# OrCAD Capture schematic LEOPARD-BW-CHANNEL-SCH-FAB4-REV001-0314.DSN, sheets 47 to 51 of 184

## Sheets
47 180_CPU - XDP: size A3; title: CPU - XDP
48 179_PCH - NOA: size A3; title: PCH - NOA
49 178_PCH - XDP: size A3; title: PCH - XDP
50 139_CPLD OTHERS: size Custom; title: CPLD OTHERS
51 138_CPLD FOR BOOT UP: size A3; title: CPLD FOR BOOT UP

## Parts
sheet 138_CPLD FOR BOOT UP
C464  SCD1U16V2KX-3GP  [C402H22]
C465  SC1KP50V2KX-1GP  [C402H22]
C466  SC1KP50V2KX-1GP  [C402H22]
C467  SC10U6D3V5KX-4GP  [C805H58]
C468  SCD1U16V2KX-3GP  [C402H22]
C469  SCD1U16V2KX-3GP  [C402H22]
C470  SCD1U16V2KX-3GP  [C402H22]
C471  SCD1U16V2KX-3GP  [C402H22]
C472  SCD1U16V2KX-3GP  [C402H22]
C473  SCD1U16V2KX-3GP  [C402H22]
C474  SCD1U16V2KX-3GP  [C402H22]
C475  SCD1U16V2KX-3GP  [C402H22]
C476  SCD01U25V2KX-3GP  [C402H22]
C477  SCD01U25V2KX-3GP  [C402H22]
CPLD1  LCMXO256C-3MN100C-GP  [BGA100G80H54]
R175  200R2J-L1-GP  [R402H16]
R176  200R2J-L1-GP  [R402H16]
R489  0R2J-2-GP  [R402H16]
R491  0R2J-2-GP  [R402H16]
R540  0R2J-2-GP  [R402H16]
R552  4K7R2J-2-GP  [R402H16]
R553  10KR2F-2-GP  [R402H16]
R554  4K75R2F-1-GP  [R402H16]
R555  10KR2F-2-GP  [R402H16]
R556  10KR2F-2-GP  [R402H16]
R557  10KR2F-2-GP  [R402H16]
R558  10KR2F-2-GP  [R402H16]
R559  1KR2F-3-GP  [R402H16]
R560  1KR2F-3-GP  [R402H16]
R561  1KR2F-3-GP  [R402H16]
R562  10KR2F-2-GP  [R402H16]
R563  0R2J-2-GP  [R402H16]
R564  0R2J-2-GP  [R402H16]
R565  0R2J-2-GP  [R402H16]
R566  0R2J-2-GP  [R402H16]
R614  10KR2F-2-GP  [R402H16]
R854  10KR2F-2-GP  [R402H16]
R858  10KR2F-2-GP  [R402H16]
R860  1KR2F-3-GP  [R402H16]
R870  10KR2F-2-GP  [R402H16]
R883  0R2J-2-GP  [R402H16]
R884  0R2J-2-GP  [R402H16]
R887  10KR2F-2-GP  [R402H16]
R1089  2KR2F-3-GP  [R402H16]
R1090  1KR2F-3-GP  [R402H16]
R1091  2KR2F-3-GP  [R402H16]
R1092  1KR2F-3-GP  [R402H16]
TP342  TPAD24  [TPAD24]
TP344  TPAD24  [TPAD24]
TP345  TPAD24  [TPAD24]
sheet 139_CPLD OTHERS
C293  SCD1U16V2KX-3GP  [C402H22]
C432  SC1U10V2KX-4-GP  [C402H22]
C481  SCD1U16V2KX-3GP  [C402H22]
C482  SCD01U25V2KX-3GP  [C402H22]
C514  SCD1U16V2KX-3GP  [C402H22]
CN51  JWT-CONN12D-SFP9-GP  [A2541WV0-2CX6PA-6T-N1]
LED46  LED-G-62-GP-U  [LED1608AKH36]
LED47  LED-G-62-GP-U  [LED1608AKH36]
LED48  LED-G-62-GP-U  [LED1608AKH36]
LED49  LED-G-62-GP-U  [LED1608AKH36]
LED50  LED-G-62-GP-U  [LED1608AKH36]
Q13  LMBT3904LT1G-GP  [SOT23CBE2D4H44]
Q14  LMBT3904LT1G-GP  [SOT23CBE2D4H44]
Q15  LMBT3904LT1G-GP  [SOT23CBE2D4H44]
Q16  LMBT3904LT1G-GP  [SOT23CBE2D4H44]
Q17  LMBT3904LT1G-GP  [SOT23CBE2D4H44]
R2  0R2J-2-GP  [R402H16]
R12  0R2J-2-GP  [R402H16]
R235  0R2J-2-GP  [R402H16]
R281  0R2J-2-GP  [R402H16]
R327  0R2J-2-GP  [R402H16]
R334  0R2J-2-GP  [R402H16]
R351  0R2J-2-GP  [R402H16]
R630  1KR2F-3-GP  [R402H16]
R631  1KR2F-3-GP  [R402H16]
R684  220R2F-GP  [R402H16]
R863  10KR2F-2-GP  [R402H16]
R864  10KR2F-2-GP  [R402H16]
R991  22R2F-1-GP  [R402H16]
R994  0R2J-2-GP  [R402H16]
R1040  10KR2F-2-GP  [R402H16]
R1093  0R2J-2-GP  [R402H16]
R1110  0R2J-2-GP  [R402H16]
R1111  0R2J-2-GP  [R402H16]
R1112  0R2J-2-GP  [R402H16]
R1119  1KR2F-3-GP  [R402H16]
R1142  2K43R2F-GP  [R402H16]
R1143  330R2J-3-GP  [R402H16]
R1144  330R2J-3-GP  [R402H16]
R1145  2K43R2F-GP  [R402H16]
R1146  2K43R2F-GP  [R402H16]
R1147  330R2J-3-GP  [R402H16]
R1148  2K43R2F-GP  [R402H16]
R1149  330R2J-3-GP  [R402H16]
R1150  2K43R2F-GP  [R402H16]
R1151  330R2J-3-GP  [R402H16]
R1152  0R2J-2-GP  [R402H16]
R1153  22R2F-1-GP  [R402H16]
R1154  10KR2F-2-GP  [R402H16]
R1256  0R2J-2-GP  [R402H16]
TP46  TPAD24  [TPAD24]
TP188  TPAD24  [TPAD24]
TP222  TPAD24  [TPAD24]
TP223  TPAD24  [TPAD24]
TP224  TPAD24  [TPAD24]
TP225  TPAD24  [TPAD24]
U81  PI3B3257QE-GP  [QSOIC16H69]
sheet 178_PCH - XDP
R1898  160R2F-GP  [R402H16]
R1899  160R2F-GP  [R402H16]
R1900  160R2F-GP  [R402H16]
R1901  51R2F-2-GP  [R402H16]
R1902  75R2F-2-GP  [R402H16]
R1903  75R2F-2-GP  [R402H16]
R1904  75R2F-2-GP  [R402H16]
R1905  4K7R2J-2-GP  [R402H16]
sheet 179_PCH - NOA
R195  10KR2F-2-GP  [R402H16]
R954  0R2J-2-GP  [R402H16]
R955  0R2J-2-GP  [R402H16]
R956  0R2J-2-GP  [R402H16]
R957  0R2J-2-GP  [R402H16]
R958  0R2J-2-GP  [R402H16]
R962  0R2J-2-GP  [R402H16]
R966  0R2J-2-GP  [R402H16]
R968  0R2J-2-GP  [R402H16]
R970  0R2J-2-GP  [R402H16]
R971  0R2J-2-GP  [R402H16]
R975  0R2J-2-GP  [R402H16]
sheet 180_CPU - XDP
C708  SC1U10V2KX-4-GP  [C402H22]
C709  SC1U10V2KX-4-GP  [C402H22]
C710  SCD1U16V2KX-3GP  [C402H22]
C711  SCD1U16V2KX-3GP  [C402H22]
C712  SCD1U16V2KX-3GP  [C402H22]
C713  SCD1U16V2KX-3GP  [C402H22]
R988  1KR2F-3-GP  [R402H16]
R989  1KR2F-3-GP  [R402H16]
R990  0R2J-2-GP  [R402H16]
R992  1KR2F-3-GP  [R402H16]
R993  475R2F-L1-GP  [R402H16]
R995  100R2F-L1-GP-U  [R402H14]
R996  100R2F-L1-GP-U  [R402H14]
R997  1KR2F-3-GP  [R402H16]
R998  150R2F-1-GP  [R402H16]
R999  1KR2F-3-GP  [R402H16]
TP301  TPAD24  [TPAD24]
TP302  TPAD24  [TPAD24]
TP303  TPAD24  [TPAD24]
TP304  TPAD24  [TPAD24]
TP305  TPAD24  [TPAD24]
TP306  TPAD24  [TPAD24]
TP307  TPAD24  [TPAD24]
TP308  TPAD24  [TPAD24]
TP309  TPAD24  [TPAD24]
TP310  TPAD24  [TPAD24]
TP311  TPAD24  [TPAD24]
TP312  TPAD24  [TPAD24]
TP442  TPAD24  [TPAD24]
XDPCN1  SMC-CONN60A-GP  [BSH-03001-FDA]

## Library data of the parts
C464 C514 = SCD1U16V2KX-3GP: CHIP CAP C 0.1U 16V K0402 X7R; CATEGORIES: CAP_1.xV; GREENDFACTOR: R2_SA;HF_SA;G_SA;; MAIN_SOURCE: M; Part Number: 78.10421.2FL; Part Type: SMD-BCG; SPEC: http://wpqssvr.wistron.com.tw:7001/wpqs/servlet/COM.qpart.Attachment?PartNumber=78.10421.2FL
C465 C466 = SC1KP50V2KX-1GP: CHIP CAP 1000P50V K0402 X7R(RO; Category: Powervill; GREENDFACTOR: R2_SA;HF_SA;G_SA;; Package Type: SMD-BCG; Part Number: 78.10224.2FL; Quotation: 9_7; Type: SMD
C467 = SC10U6D3V5KX-4GP: CHIP CAP C 10U 6.3V K0805 X7R; Category: CLK GEN; GREENDFACTOR: R_SA;HF_SA;G_SA;; Part Number: 78.10620.21L; Quotation: 13_8; Type: SMD
C293 C468-C475 C481 C710-C713 = SCD1U16V2KX-3GP: CHIP CAP C 0.1U 16V K0402 X7R; Category: CLK GEN; GREENDFACTOR: R_SA;HF_SA;G_SA;; Part Number: 78.10421.2FL; Quotation: 13_8; Type: SMD
C476 C477 C482 = SCD01U25V2KX-3GP: CHIP 0.01U 25V K0402 X7R(ROHS); Category: CLK GEN; GREENDFACTOR: R2_SA;HF_SA;G_SA;; Package Type: SMD-BCG; Part Number: 78.10322.2FL; Quotation: 13_8; Type: SMD
CPLD1 = LCMXO256C-3MN100C-GP: IC CPLD LCMXO256C-3MN100C CSBGA 100P; POP?: 073.00256.0I0U; Part Number: 73.00256.0VU; Part Type: ASIC-G3
R175 R176 = 200R2J-L1-GP: CHIP RES 200 J 1/16W 0402; Category: CPU SIDE BAND; Part Number: 63.20134.1DL; Part Type: SMD-RG
R489 R491 R540 = 0R2J-2-GP: CHIP RES 0 J 1/16W 0402; Category: PCH; DESCRIPTIO: CHIP RES 0 J 1/16W 0402; GREENDFACTOR: R2_SA;HF_SA;G_SA;; Package Type: SMD-RG; Part Number: 63.R0034.1DL; Part Type: SMD-RG; SPEC: http://wpqssvr.wistron.com.tw:7001/wpqs/servlet/COM.qpart.Attachment?PartNumber=63.R0034.1DL; VENDORPARTNUMBER: RM04JTN0/RTT02000JTH/RR0510X-000-XN/RC0402JR-070RL/WR04X000 PTL
R552 = 4K7R2J-2-GP: CHIP RES 4.7K J 1/16W 0402; Category: SMBUS; GREENDFACTOR: R_SA;HF_SA;G_SA;; Part Number: 63.47234.1DL; Quotation: 8_1; Type: SMD
R553 R556-R558 R562 R614 R858 R863 R864 R870 R887 R1040 = 10KR2F-2-GP: CHIP RES 10K F 1/16W 0402; Category: MSIC; DESCRIPTIO: CHIP RES 10K F 1/16W 0402; GREENDFACTOR: R2_SA;HF_SA;G_SA;; Package Type: SMD-RG; Part Number: 64.10025.6DL; Part Type: SMD-RG; SPEC: http://wpqssvr.wistron.com.tw:7001/wpqs/servlet/COM.qpart.Attachment?PartNumber=64.10025.6DL; VENDORPARTNUMBER: RM04FTN1002 / RTT021002FTH / RR0510S-103-FN / RC0402FR-0710KL/WR04X1002FTL
R554 = 4K75R2F-1-GP: CHIP RES 4.75K F 1/16W 0402; Category: VR_DDR; GREENDFACTOR: R2_SA;HF_SA;G_SA;; Package Type: RCL_GP; Part Number: 64.47515.6DL; Part Type: RCL_GP; SPEC: http://wpqssvr.wistron.com.tw:7001/wpqs/servlet/COM.qpart.Attachment?PartNumber=64.47515.6DL; VENDORPARTNUMBER: RM04FTN4751/RTT024751FTH/RR0510S-4751-FN/RC0402FR-074K75L
R555 R854 R1154 = 10KR2F-2-GP: CHIP RES 10K F 1/16W 0402; Category: MSIC; DESCRIPTIO: CHIP RES 10K F 1/16W 0402; GREENDFACTOR: R2_SA;HF_SA;G_SA;; POP?: NOPOP; Package Type: SMD-RG; Part Number: 64.10025.6DL; Part Type: SMD-RG; SPEC: http://wpqssvr.wistron.com.tw:7001/wpqs/servlet/COM.qpart.Attachment?PartNumber=64.10025.6DL; VENDORPARTNUMBER: RM04FTN1002 / RTT021002FTH / RR0510S-103-FN / RC0402FR-0710KL/WR04X1002FTL
R559 R631 R988 R989 R992 R997 R999 = 1KR2F-3-GP: CHIP RES 1K F 1/16W 0402; Category: internal conn; GREENDFACTOR: R2_SA;HF_SA;G_SA;; Package Type: SMD-RG; Part Number: 64.10015.6DL; Part Type: SMD-RG; SPEC: http://wpqssvr.wistron.com.tw:7001/wpqs/servlet/COM.qpart.Attachment?PartNumber=64.10015.6DL; VENDORPARTNUMBER: RM04FTN1001 / RTT021001FTH / RR0510S-1001-FN / RC0402FR-071KL/WR04X1001FTL
R560 R561 R630 R860 R1119 = 1KR2F-3-GP: CHIP RES 1K F 1/16W 0402; Category: internal conn; GREENDFACTOR: R2_SA;HF_SA;G_SA;; POP?: NOPOP; Package Type: SMD-RG; Part Number: 64.10015.6DL; Part Type: SMD-RG; SPEC: http://wpqssvr.wistron.com.tw:7001/wpqs/servlet/COM.qpart.Attachment?PartNumber=64.10015.6DL; VENDORPARTNUMBER: RM04FTN1001 / RTT021001FTH / RR0510S-1001-FN / RC0402FR-071KL/WR04X1001FTL
R563-R566 R954-R956 R958 R966 R968 R970 R971 R975 R990 = 0R2J-2-GP: CHIP RES 0 J 1/16W 0402; Category: BMC; DESCRIPTIO: CHIP RES 0 J 1/16W 0402; GREENDFACTOR: R2_SA;HF_SA;G_SA;; Package Type: SMD-RG; Part Number: 63.R0034.1DL; Part Type: SMD-RG; SPEC: http://wpqssvr.wistron.com.tw:7001/wpqs/servlet/COM.qpart.Attachment?PartNumber=63.R0034.1DL; VENDORPARTNUMBER: RM04JTN0/RTT02000JTH/RR0510X-000-XN/RC0402JR-070RL/WR04X000 PTL
R883 R884 R957 R962 = 0R2J-2-GP: CHIP RES 0 J 1/16W 0402; Category: BMC; DESCRIPTIO: CHIP RES 0 J 1/16W 0402; GREENDFACTOR: R2_SA;HF_SA;G_SA;; POP?: NOPOP; Package Type: SMD-RG; Part Number: 63.R0034.1DL; Part Type: SMD-RG; SPEC: http://wpqssvr.wistron.com.tw:7001/wpqs/servlet/COM.qpart.Attachment?PartNumber=63.R0034.1DL; VENDORPARTNUMBER: RM04JTN0/RTT02000JTH/RR0510X-000-XN/RC0402JR-070RL/WR04X000 PTL
R1089 R1091 = 2KR2F-3-GP: CHIP RES 2K F 1/16W 0402; Category: internal conn; DESCRIPTIO: CHIP RES 2K F 1/16W 0402; GREENDFACTOR: R2_SA;HF_SA;G_SA;; Package Type: SMD-RG; Part Number: 64.20015.6DL; Part Type: SMD-RG; SPEC: http://wpqssvr.wistron.com.tw:7001/wpqs/servlet/COM.qpart.Attachment?PartNumber=64.20015.6DL; VENDORPARTNUMBER: RM04FTN2001 / RTT022001FTH / RR0510S-202-FN / RC0402FR-072KL/WR04X2001FTL
R1090 R1092 = 1KR2F-3-GP: CHIP RES 1K F 1/16W 0402; GREENDFACTOR: R2_SA;HF_SA;G_SA;; Part Number: 64.10015.6DL; Part Type: SMD-RG; SPEC: http://wpqssvr.wistron.com.tw:7001/wpqs/servlet/COM.qpart.Attachment?PartNumber=64.10015.6DL
TP46 TP188 TP222-TP225 TP301-TP312 TP342 TP344 TP345 TP442 = TPAD24: 24 MILS TEST PAD; Part Number: ZZ.PAD24.001; Part Type: DISCRET2
C432 = SC1U10V2KX-4-GP: CHIP CAP C 1U 10V K 0402 X6S; GREENDFACTOR: R2_SA;HF_SA;; POP?: NOPOP; Part Number: 78.10523.8FL; Part Type: SMD-BCG6; SPEC: http://wpqssvr.wistron.com.tw:7001/wpqs/servlet/COM.qpart.Attachment?PartNumber=78.10523.8FL
CN51 = JWT-CONN12D-SFP9-GP: HEAD ML 2R12P(-1#11) A2541WV0-2CX6PA-6T; GREENDFACTOR: R2_SA;; Part Number: 21.62906.206; Part Type: CONN-G3; SPEC: http://wpqssvr.wistron.com.tw:7001/wpqs/servlet/COM.qpart.Attachment?PartNumber=21.62906.206
LED46-LED50 = LED-G-62-GP-U: LED GREEN LTST-C190GKT SMD; GREENDFACTOR: R2_SA;; Package Type: DISCRET-G9; Part Number: 83.00190.Q70; SPEC: http://wpqssvr.wistron.com.tw:7001/wpqs/servlet/COM.qpart.Attachment?PartNumber=83.00190.Q70
Q13-Q17 = LMBT3904LT1G-GP: XTOR LMBT3904LT1G NPN SOT-23; GREENDFACTOR: R2_SA;HF_SA;G_SA;; Part Number: 84.T3904.H11; Part Type: DISCRET-G6; SPEC: http://wpqssvr.wistron.com.tw:7001/wpqs/servlet/COM.qpart.Attachment?PartNumber=84.T3904.H11
R2 R12 R235 R281 R327 R334 R351 R1152 R1256 = 0R2J-2-GP: CHIP RES 0 J 1/16W 0402; Category: LOM - i350; DESCRIPTIO: CHIP RES 0 J 1/16W 0402; GREENDFACTOR: R2_SA;HF_SA;G_SA;; POP?: NOPOP; Package Type: SMD-RG; Part Number: 63.R0034.1DL; Part Type: SMD-RG; SPEC: http://wpqssvr.wistron.com.tw:7001/wpqs/servlet/COM.qpart.Attachment?PartNumber=63.R0034.1DL; VENDORPARTNUMBER: RM04JTN0/RTT02000JTH/RR0510X-000-XN/RC0402JR-070RL/WR04X000 PTL
R684 = 220R2F-GP: CHIP RES 220 F 1/16W 0402; Category: CPU0; GREENDFACTOR: R2_SA;HF_SA;G_SA;; Package Type: RCL_GP; Part Number: 64.22005.6DL; SPEC: http://wpqssvr.wistron.com.tw:7001/wpqs/servlet/COM.qpart.Attachment?PartNumber=64.22005.6DL
R991 R1153 = 22D1R2F-GP: CHIP RES 22 F 1/16W 0402(ROHS); Category: Logic; DESCRIPTIO: CHIP RES 22.1 F 1/16W 0402; GREENDFACTOR: R2_SA;HF_SA;G_SA;; Package Type: SMD-RG; Part Number: 64.22R05.6DL; Part Type: SMD-RG; SPEC: http://wpqssvr.wistron.com.tw:7001/wpqs/servlet/COM.qpart.Attachment?PartNumber=64.22R05.6DL; VENDORPARTNUMBER: RM04FTN22R0/RTT0222R0FTH/RR0510S-220-FN/RC0402FR-0722RL
R994 R1093 R1110-R1112 = 0R2J-2-GP: CHIP RES 0 J 1/16W 0402; Category: LOM - i350; DESCRIPTIO: CHIP RES 0 J 1/16W 0402; GREENDFACTOR: R2_SA;HF_SA;G_SA;; Package Type: SMD-RG; Part Number: 63.R0034.1DL; Part Type: SMD-RG; SPEC: http://wpqssvr.wistron.com.tw:7001/wpqs/servlet/COM.qpart.Attachment?PartNumber=63.R0034.1DL; VENDORPARTNUMBER: RM04JTN0/RTT02000JTH/RR0510X-000-XN/RC0402JR-070RL/WR04X000 PTL
R1142 R1145 R1146 R1148 R1150 = 2K43R2F-GP: CHIP RES 2.43K F 1/16W 0402; GREENDFACTOR: R2_SA;HF_SA;G_SA;; Package Type: RCL_GP; Part Number: 64.24315.6DL; SPEC: http://wpqssvr.wistron.com.tw:7001/wpqs/servlet/COM.qpart.Attachment?PartNumber=64.24315.6DL
R1143 R1144 R1147 R1149 R1151 = 330R2J-3-GP: CHIP RES 330 J 1/16W 0402; Category: HW monitor; DESCRIPTIO: CHIP RES 330 J 1/16W 0402; GREENDFACTOR: R2_SA;HF_SA;G_SA;; Package Type: SMD-RG; Part Number: 63.33134.1DL; Part Type: SMD-RG; SPEC: http://wpqssvr.wistron.com.tw:7001/wpqs/servlet/COM.qpart.Attachment?PartNumber=63.33134.1DL; VENDORPARTNUMBER: RM04JTN331 / RTT02331JTH / RR0510S-331-JN / RC0402JR-07330RL/WR04X331JTL
U81 = PI3B3257QE-GP: IC BUS SW PI3B3257QE QSOP 16P; GREENDFACTOR: R2_SA;; Package Type: DISCRET-G2; Part Number: 73.33257.A0C; SPEC: http://wpqssvr.wistron.com.tw:7001/wpqs/servlet/COM.qpart.Attachment?PartNumber=73.33257.A0C
R1898-R1900 = 160R2F-GP: CHIP RES 160 F 1/16W 0402; GREENDFACTOR: R2_SA;HF_SA;G_SA;; Package Type: SMD-RG1; Part Number: 64.16005.6DL; SPEC: http://wpqssvr.wistron.com.tw:7001/wpqs/servlet/COM.qpart.Attachment?PartNumber=64.16005.6DL
R1901 = 51D1R2F-GP: CHIP RES 51 F 1/16W 0402; Category: XDP; DESCRIPTIO: CHIP RES 51.1 F 1/16W 0402; GREENDFACTOR: R2_SA;HF_SA;G_SA;; Package Type: SMD-RG; Part Number: 64.51R05.6DL; Part Type: SMD-RG; SPEC: http://wpqssvr.wistron.com.tw:7001/wpqs/servlet/COM.qpart.Attachment?PartNumber=64.51R05.6DL; VENDORPARTNUMBER: RM04FTN51R0/RTT0251R0FTH/RR0510S-510-FN/RC0402FR-0751RL/WR04X51R0FTL
R1902-R1904 = 75R2F-2-GP: CHIP RES 75 F 1/16W 0402; Category: XDP; DESCRIPTIO: CHIP RES 75 F 1/16W 0402; GREENDFACTOR: R2_SA;HF_SA;G_SA;; Package Type: SMD-RG; Part Number: 64.75R05.6DL; Part Type: SMD-RG; SPEC: http://wpqssvr.wistron.com.tw:7001/wpqs/servlet/COM.qpart.Attachment?PartNumber=64.75R05.6DL; VENDORPARTNUMBER: RM04FTN75R0 / RTT0275R0FTH / RR0510S-750-FN / RC0402FR-0775RL/WR04X75R0FTL
R1905 = 4K7R2J-2-GP: CHIP RES 4.7K J 1/16W 0402; Category: PCH; GREENDFACTOR: R_SA;HF_SA;G_SA;; Part Number: 63.47234.1DL; Quotation: 8_1; Type: SMD
R195 = 10KR2F-2-GP: CHIP RES 10K F 1/16W 0402; Category: PCH; DESCRIPTIO: CHIP RES 10K F 1/16W 0402; GREENDFACTOR: R2_SA;HF_SA;G_SA;; Package Type: SMD-RG; Part Number: 64.10025.6DL; Part Type: SMD-RG; SPEC: http://wpqssvr.wistron.com.tw:7001/wpqs/servlet/COM.qpart.Attachment?PartNumber=64.10025.6DL; VENDORPARTNUMBER: RM04FTN1002 / RTT021002FTH / RR0510S-103-FN / RC0402FR-0710KL/WR04X1002FTL
C708 C709 = SC1U10V2KX-4-GP: CHIP CAP C 1U 10V K 0402 X6S; GREENDFACTOR: R2_SA;HF_SA;; Part Number: 78.10523.8FL; Part Type: SMD-BCG6; SPEC: http://wpqssvr.wistron.com.tw:7001/wpqs/servlet/COM.qpart.Attachment?PartNumber=78.10523.8FL
R993 = 475R2F-L1-GP: CHIP RES 475 F 1/16W 0402; Category: Clock; DESCRIPTIO: CHIP RES 475 F 1/16W 0402; GREENDFACTOR: R2_SA;HF_SA;G_SA;; Package Type: SMD-RG; Part Number: 64.47505.6DL; Part Type: SMD-RG; SPEC: http://wpqssvr.wistron.com.tw:7001/wpqs/servlet/COM.qpart.Attachment?PartNumber=64.47505.6DL; VENDORPARTNUMBER: RM04FTN4750 / RTT024750FTH / RR0510S-4750-FN / RC0402FR-07475RL/WR04X4750FTL
R995 R996 = 100R2F-L1-GP-U: CHIP RES 100 F 1/16W 0402; Category: CPU SIDE BAND; Part Number: 64.10005.6DL; Part Type: SMD-RG
R998 = 150R2F-1-GP: CHIP RES 150 F 1/16W 0402; Category: VR_DDR; DESCRIPTIO: CHIP RES 150 F 1/16W 0402; GREENDFACTOR: R2_SA;HF_SA;G_SA;; Package Type: SMD-RG; Part Number: 64.15005.6DL; Part Type: SMD-RG; SPEC: http://wpqssvr.wistron.com.tw:7001/wpqs/servlet/COM.qpart.Attachment?PartNumber=64.15005.6DL; VENDORPARTNUMBER: RM04FTN1500 / RTT021500FTH / RR0510S-1500-FN / RC0402FR-07150RL/WR04X1500FTL
XDPCN1 = SMC-CONN60A-GP: CONN SMD 60P BSH-030-01-L-D-A-; Category: XDP; DESCRIPTIO: CONN SMD 60P BSH-030-01-L-D-A-; GREENDFACTOR: R2_SA;HF_SA;; Note: The same as CRB; Package Type: CONN-G6; Part Number: 20.F0441.060; Part Type: CONN-G6; SPEC: http://wpqssvr.wistron.com.tw:7001/wpqs/servlet/COM.qpart.Attachment?PartNumber=20.F0441.060; VENDORPARTNUMBER: BSH-030-01-L-D-A-TR

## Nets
GND: C293.2 C432.2 C464.2 C465.2 C466.2 C467.2 C468.2 C469.2 C470.2 C471.2 C472.2 C473.2 C474.2 C475.2 C476.2 C477.2 C481.2 C482.2 C514.2 C708.2 C709.2 C710.2 C711.2 C712.2 C713.2 CN51.1 CN51.12 CPLD1.A4(GNDIO0) CPLD1.B9(GND) CPLD1.B13(GNDIO0) CPLD1.C13(PR3B) CPLD1.G14(GNDIO0) CPLD1.H1(GNDIO1) CPLD1.N2(GNDIO1) CPLD1.N3(PB2B) CPLD1.N9(GND) CPLD1.N10(GNDIO1) Q13.E Q14.E Q15.E Q16.E Q17.E R554.2 R558.2 R559.2 R560.2 R561.2 R562.2 R630.2 R631.2 R684.2 R860.2 R870.2 R1040.1 R1089.2 R1090.2 R1091.2 R1092.1 R1256.1 R1901.2 R1902.2 R1903.2 R1904.2 TP225.1 U81.8(GND) XDPCN1.1 XDPCN1.2 XDPCN1.7 XDPCN1.8 XDPCN1.13 XDPCN1.14 XDPCN1.19 XDPCN1.20 XDPCN1.25 XDPCN1.26 XDPCN1.31 XDPCN1.32 XDPCN1.37 XDPCN1.38 XDPCN1.49 XDPCN1.50 XDPCN1.59 ; also on sheet 1 2 3 4 5 6 7 8 9 10 11 12 13 14 15 16 17 18 19 20 21 22 23 24 25 26 27 28 29 30 31 32 33 34 35 36 37 38 39 44 46 52 53 54 55 56 57 58 59 60 61 62 63 64 65 66 69 70 71 73 74 75 76 78 79 80 81 82 83 84 86 87 88 89 90 91 92 93 94 95 96 97 98 99 100 101 102 103 104 105 106 107 108 109 110 111 112 113 114 115 116 117 118 119 128 129 138 139 159 160 161 166 168 169 170 171 172 173 174 175 176 177 180 181 182 183 184
P3V3: R195.1 R1905.1 ; also on sheet 1 3 8 45 46 52 54 58 65 74 76 78 83 84 87 90 91 94 95 96 100 101 102 161 166 168 173 174 177 180 181 182 183
P3V3_STBY: C293.1 C432.1 C467.1 C468.1 C469.1 C470.1 C471.1 C472.1 C473.1 C474.1 C475.1 C476.1 C477.1 C481.1 C482.1 C514.1 CN51.2 CPLD1.A14(VCCIO0) CPLD1.B5(VCCIO0) CPLD1.B6(VCC) CPLD1.B7(VCCAUX) CPLD1.G1(VCCIO1) CPLD1.H14(VCCIO0) CPLD1.P1(VCCIO1) CPLD1.P7(VCC) CPLD1.P10(VCCIO1) R175.1 R176.1 R552.1 R553.1 R555.1 R556.1 R557.1 R614.1 R854.1 R858.1 R863.1 R864.1 R887.2 R992.2 R997.2 R999.2 R1119.1 R1143.1 R1144.2 R1147.2 R1149.2 R1151.2 R1154.1 R1898.1 R1899.1 R1900.1 U81.16(VCC) ; also on sheet 2 3 5 6 8 9 10 11 12 15 16 17 20 21 22 25 26 27 30 31 33 34 35 37 38 39 45 52 54 55 59 60 61 62 63 64 65 66 69 70 71 72 73 74 76 79 83 84 87 88 89 90 91 92 93 94 95 96 97 98 99 159 161 166 168 173 174 176 177 179 180 182 183 184
PVCCIN_CPU0_EN: CPLD1.D2(PL3A) R1089.1 ; also on sheet 39
PVCCIN_CPU1_EN: CPLD1.K2(PL7A) R1091.1 ; also on sheet 35
PVCCIO: C708.1 C709.1 R993.2 R995.2 R996.2 R998.2 XDPCN1.43 XDPCN1.44 ; also on sheet 11 16 26 35 39 46 68 87 97 100 101 102 103 120 129 130 139 160 173 177 179 182
ARM_TCK: R2.1 R12.1 R1110.1 ; also on sheet 177
ARM_TDI: R334.1 R1112.1 ; also on sheet 177
ARM_TDO: R351.1 R1111.1 ; also on sheet 177
ARM_TMS: R235.1 R281.1 R1093.1 ; also on sheet 177
BMC_JTAG_SELECT: R1040.2 R1119.2 U81.1(S) ; also on sheet 74
BMC_READY_R: CPLD1.J13(PR6B) R884.1
BMC_RESET_N: R883.2 ; also on sheet 74 177
BMC_RESET_R_N: CPLD1.L14(PR8A) R883.1
BMC_TCK: R1110.2 U81.12(4A)
BMC_TDI: R1112.2 U81.7(2A)
BMC_TDO: R1111.2 U81.4(1A)
BMC_TMS: R1093.2 U81.9(3A)
BOARD_ID0_PCH: R966.2 ; also on sheet 71
BOARD_ID2_PCH: R968.2 ; also on sheet 71
CLK_32K_SUSCLK_NGFF: R1152.2 ; also on sheet 83
CLK_32K_SUSCLK_PLD: R991.1 ; also on sheet 55
CLK_32K_SUSCLK_PLD_R: R991.2 R1152.1
CLK_33K_SUSCLK_PLD: R1153.1 ; also on sheet 90 174
CLK_33K_SUSCLK_PLD_R: R994.1 R1153.2
CLK_33K_SUSCLK_PLD_R2: CPLD1.A7(PT3D) R994.2
CLK_100M_XDP_DN: XDPCN1.42 ; also on sheet 88
CLK_100M_XDP_DP: XDPCN1.40 ; also on sheet 88
CPLD1_OK_HB: CPLD1.A6(PT3C) ; also on sheet 177
CPU_CACHE_FLUSH_TRIGGER_N: R962.1 ; also on sheet 92
FM_ADR_COMPLETE: R540.2 ; also on sheet 166 177
FM_ADR_COMPLETE_CPLD_SAVE: CPLD1.B11(PT5B) ; also on sheet 52
FM_BMC_READY_N: R884.2 ; also on sheet 52 74 166
FM_CPLD_ADR_COMPLETE: CPLD1.N14(PR9B) R540.1
FM_CPU0_BDX_PRSNT_LVT3_N: CPLD1.L1(PL7B) ; also on sheet 11 139 179
FM_CPU0_SKTOCC_LVT3_N: CPLD1.M3(PL9A) ; also on sheet 46 139 179
FM_CPU1_BDX_PRSNT_LVT3_N: CPLD1.D1(PL3B) ; also on sheet 129 179
FM_CPU1_SKTOCC_LVT3_N: CPLD1.J2(PL6A) ; also on sheet 46 129 179
FM_CPU_ERR1_CO_N: CPLD1.L2(PL7C) R552.2 ; also on sheet 102 177
FM_CPU_PROCHOT_N: R195.2 R971.2 ; also on sheet 98
FM_ERR1_DLY_N: CPLD1.B10(PT4D) ; also on sheet 166
FM_LVC3_THERMTRIP_DLY: CPLD1.P14(PB5C) ; also on sheet 182
FM_P3V3_CPLD_EN: CPLD1.G2(PL5B) ; also on sheet 3
FM_PCH_PRSNT_CO_N: CPLD1.B8(PT4A) ; also on sheet 89
FM_PERST_SRC_LVT3: CPLD1.P11(PB4A) R631.1 R1154.2
FM_PLD_CLK_EN: CPLD1.B3(PT2E) ; also on sheet 58
FM_PLD_DEBUG1: CPLD1.L13(PR8B) R863.2 R1142.1 R1256.2 TP46.1
FM_PLD_DEBUG1_R: Q13.B R1142.2
FM_PLD_DEBUG2: CPLD1.A9(PT4C) R1145.1 TP188.1
FM_PLD_DEBUG2_R: Q14.B R1145.2
FM_PLD_DEBUG3: CPLD1.A5(PT3B) R1146.1 TP222.1
FM_PLD_DEBUG3_R: Q15.B R1146.2
FM_PLD_DEBUG4: CPLD1.G13(PR5D) R1148.1 TP223.1
FM_PLD_DEBUG4_R: Q16.B R1148.2
FM_PLD_DEBUG5: CPLD1.A3(PT2F) R1150.1 TP224.1
FM_PLD_DEBUG5_R: Q17.B R1150.2
FM_PLD_DEBUG_MODE_N: CPLD1.M2(PL8A) R630.1 R864.2
FM_PLD_RESET_N: CPLD1.J1(PL5D) R556.2 R560.1
FM_PLD_TSALL: CPLD1.K1(PL6B) R555.2 R559.1
FM_PS_EN: CPLD1.A2(PT2D) ; also on sheet 59 93
FM_SLPS3_N: CPLD1.B4(PT3A) ; also on sheet 52 59 74 90
FM_SLPS4_N: CPLD1.A1(PT2B) ; also on sheet 74 90
FM_THERMTRIP_CO_N: CPLD1.M1(PL7D) R553.2 ; also on sheet 98
FM_VCC_MAIN_EN: CPLD1.A8(PT4B) ; also on sheet 10 11
FM_VPP_MEM_ABCD_EN: CPLD1.N11(PB4B) R1092.2 ; also on sheet 22 27
FM_VPP_MEM_EFGH_EN: CPLD1.J14(PR7A) R1090.1 ; also on sheet 12 17
FM_XDP_HOOK1_SEL: CPLD1.P8(PB3B) R858.2 R860.1
FP_PWR_BTN_N: CPLD1.N7(PB3A) ; also on sheet 168
IRQ_SML1_PMBUS_ALERT_BUF_N: CPLD1.E13(PR4B) ; also on sheet 52 183
JTAG_PLD1_TCK: CN51.7 R12.2 U81.13(4B2) ; also on sheet 52
JTAG_PLD1_TDI: CN51.3 R327.2 U81.6(2B2) ; also on sheet 52
JTAG_PLD1_TDO: CN51.9 R351.2 U81.3(1B2) ; also on sheet 52
JTAG_PLD1_TMS: CN51.5 R281.2 U81.10(3B2) ; also on sheet 52
JTAG_PLD_TCK: CN51.6 CPLD1.N4(TCK) R2.2 R554.1 U81.14(4B1)
JTAG_PLD_TDI: CN51.10 CPLD1.P6(TDI) R334.2 U81.5(2B1)
JTAG_PLD_TDO: CN51.4 CPLD1.P5(TDO) R327.1 U81.2(1B1) ; also on sheet 84
JTAG_PLD_TMS: CN51.8 CPLD1.P2(TMS) R235.2 U81.11(3B1)
LED_DEBUG1: LED46.A R1143.2
LED_DEBUG1_R: LED46.K Q13.C
LED_DEBUG2: LED47.A R1144.1
LED_DEBUG2_R: LED47.K Q14.C
LED_DEBUG3: LED48.A R1147.1
LED_DEBUG3_R: LED48.K Q15.C
LED_DEBUG4: LED49.A R1149.1
LED_DEBUG4_R: LED49.K Q16.C
LED_DEBUG5: LED50.A R1151.1
LED_DEBUG5_R: LED50.K Q17.C
NOA_0_FM_USB_OC_0_N: R954.1 ; also on sheet 92
NOA_1_FM_USB_OC_1_N: R956.1 ; also on sheet 92
NOA_2_FM_USB_OC_2_N: R957.1 ; also on sheet 92
NOA_3_FM_USB_OC_3_N: R958.1 ; also on sheet 92
NOA_5_FM_USB_OC_5_N: R966.1 ; also on sheet 92
NOA_6_FM_USB_OC_6_N: R968.1 ; also on sheet 92
NOA_7_FM_USB_OC_7_N: R970.1 ; also on sheet 92
NOA_9_RST_PCIE_PCH_N: R955.1 R1905.2 ; also on sheet 91
NOA_13_FM_CPU_PROCHOT_N: R971.1 ; also on sheet 91
NOA_14_GP18_TP: R975.1 ; also on sheet 90
NVDIMM_PRSNT_R: CPLD1.B14(PR3A) ; also on sheet 177
PCH_GP56_PLD_TCK: R854.2 ; also on sheet 166
POWER_FAIL_1_R: R957.2 ; also on sheet 54
POWER_FAIL_N: R962.2 ; also on sheet 52 54 61 93 177
PU_PLD_SLEEP_N: CPLD1.M12(SLEEP#) R557.2 R561.1
PWRGD_CPU0_G: R988.1 ; also on sheet 97 139
PWRGD_CPU0_LVC3: R563.2 ; also on sheet 97
PWRGD_CPU0_LVC3_R: CPLD1.C3(PT2C) R563.1
PWRGD_CPU1_LVC3: R564.1 ; also on sheet 97
PWRGD_CPU1_LVC3_R: CPLD1.E2(PL4A) R564.2
PWRGD_CPUPWRGD: CPLD1.B1(PL2A) ; also on sheet 182
PWRGD_LOM_AUX_VRS: CPLD1.C12(PR2B) R887.1
PWRGD_P1V05_PCH: CPLD1.C2(PL3C) ; also on sheet 10
PWRGD_P1V5_PCH: CPLD1.N1(PL8B) ; also on sheet 8 11
PWRGD_P1V05_PCH_STBY_DLY: CPLD1.P3(PL9B) ; also on sheet 90 174
PWRGD_P1V05_STBY_PCH_P1V0_STBY: CPLD1.P4(PB2A) ; also on sheet 9
PWRGD_P3V3: CPLD1.B12(PT4F) ; also on sheet 3 8
PWRGD_P5V: CPLD1.P9(PB3D) ; also on sheet 59
PWRGD_PCH_PWROK: CPLD1.C1(PL2B) ; also on sheet 52 90 174
PWRGD_PS_PWROK: C464.1 CPLD1.F1(PL4B) ; also on sheet 59 65
PWRGD_PVCCIN_CPU0: C465.1 CPLD1.A13(PR2A) ; also on sheet 39 58
PWRGD_PVCCIN_CPU1: C466.1 CPLD1.A10(PT4E) ; also on sheet 35
PWRGD_PVPP_PVDDQ_AB: CPLD1.P12(PB4C) ; also on sheet 31
PWRGD_PVPP_PVDDQ_CD: CPLD1.N12(PB4D) ; also on sheet 26
PWRGD_PVPP_PVDDQ_EF: CPLD1.E14(PR5A) ; also on sheet 21
PWRGD_PVPP_PVDDQ_GH: CPLD1.H13(PR6A) ; also on sheet 16
PWRGD_SYS_PWROK: CPLD1.H2(PL5C) ; also on sheet 52 90 174
REVISION_ID3_PCH: R970.2 ; also on sheet 71
ROMA0: R958.2 ; also on sheet 72 180
RST_CPU0_G_N: R989.2 ; also on sheet 97 139
RST_CPU0_LVC3_N: R565.1 ; also on sheet 97 99
RST_CPU0_LVC3_R_N: CPLD1.F2(PL5A) R565.2
RST_CPU1_LVC3_N: R566.1 ; also on sheet 97 99
RST_CPU1_LVC3_R_N: CPLD1.E1(PL3D) R566.2
RST_DLY_CPURST_LVC3: CPLD1.C14(PR3C) ; also on sheet 181
RST_PCIE_CPU_N: CPLD1.M14(PR9A) R614.2 ; also on sheet 90
RST_PCIE_PCH_DEV_N: CPLD1.M13(PR7D) R870.1 ; also on sheet 64 74 83
RST_PCIE_PCH_N: CPLD1.K13(PR7B) R955.2 ; also on sheet 174
RST_PERST0_N: CPLD1.K14(PR7C) R562.1 ; also on sheet 93 94 95 168
RST_PERST1_N: R491.2 R558.1 TP345.1
RST_PERST1_R_N: CPLD1.F14(PR5C) R491.1
RST_PLTRST_BUF_N: R489.2 ; also on sheet 52 78 177
RST_PLTRST_BUF_N_R: CPLD1.F13(PR5B) R489.1
RST_PLTRST_DLY: CPLD1.A12(PT5C) ; also on sheet 183
RST_PLTRST_N: CPLD1.N8(PB3C) ; also on sheet 90 100 174 177
RST_RSMRST_N: CPLD1.P13(PB5A) ; also on sheet 52 177 182
SGPIO_BMC_CLK_BUF_LVC3: CPLD1.A11(PT5A) R176.2 TP342.1
SMB_HOST_STBY_LVC3_CLK: XDPCN1.53 ; also on sheet 55 74 77 90 161
SMB_HOST_STBY_LVC3_DATA: XDPCN1.51 ; also on sheet 55 74 77 90 161
SRP_CPU_PWR_DEBUG_N: C712.1 R998.1 XDPCN1.45 ; also on sheet 128 138
SSB_ROW_LATCH: R975.2 ; also on sheet 168
TP_SGPIO_BMC_LD_BUF_LVC3_N: CPLD1.D13(PR3D) R175.2 TP344.1
TP_XDP_CPU_OBSDATA_C_MBP2: TP303.1 XDPCN1.10
TP_XDP_CPU_OBSDATA_C_MBP3: TP304.1 XDPCN1.12
TP_XDP_CPU_OBSDATA_C_MBP4: TP305.1 XDPCN1.16
TP_XDP_CPU_OBSDATA_C_MBP5: TP306.1 XDPCN1.18
TP_XDP_CPU_OBSDATA_D_MBP2: TP309.1 XDPCN1.28
TP_XDP_CPU_OBSDATA_D_MBP3: TP310.1 XDPCN1.30
TP_XDP_CPU_OBSDATA_D_MBP4: TP311.1 XDPCN1.34
TP_XDP_CPU_OBSDATA_D_MBP5: TP312.1 XDPCN1.36
TP_XDP_CPU_OBSFN_C0: TP301.1 XDPCN1.4
TP_XDP_CPU_OBSFN_C1: TP302.1 XDPCN1.6
TP_XDP_CPU_OBSFN_D0: TP307.1 XDPCN1.22
TP_XDP_CPU_OBSFN_D1: TP308.1 XDPCN1.24
TP_XDP_CPU_TCK1: TP442.1 XDPCN1.55
U81_EN_N: R684.1 U81.15(OE#)
USB2_OC0_INT_N: R954.2 ; also on sheet 176
USB2_OC1_FP_N: R956.2 ; also on sheet 176
XDP_CPU0_OBSDATA_A_MBP2_G_N: XDPCN1.9 ; also on sheet 139
XDP_CPU0_OBSDATA_A_MBP3_G_N: XDPCN1.11 ; also on sheet 139
XDP_CPU0_OBSDATA_A_MBP4_G_N: XDPCN1.15 ; also on sheet 139
XDP_CPU0_OBSDATA_A_MBP5_G_N: XDPCN1.17 ; also on sheet 139
XDP_CPU0_PRDY_G_N: XDPCN1.5 ; also on sheet 46 139
XDP_CPU0_PREQ_G_N: XDPCN1.3 ; also on sheet 46 139
XDP_CPU1_OBSDATA_B_MBP2_G_N: XDPCN1.27 ; also on sheet 129
XDP_CPU1_OBSDATA_B_MBP3_G_N: XDPCN1.29 ; also on sheet 129
XDP_CPU1_OBSDATA_B_MBP4_G_N: XDPCN1.33 ; also on sheet 129
XDP_CPU1_OBSDATA_B_MBP5_G_N: XDPCN1.35 ; also on sheet 129
XDP_CPU_OBSFN_B_MBP6_G_N: R996.1 XDPCN1.21 ; also on sheet 129 139
XDP_CPU_OBSFN_B_MBP7_G_N: R995.1 XDPCN1.23 ; also on sheet 129 139
XDP_CPU_PWRGD: R988.2 XDPCN1.39
XDP_CPU_RST_N: R989.1 XDPCN1.46
XDP_CPU_SYSPWROK: C710.1 CPLD1.D14(PR4A) R992.1 XDPCN1.47
XDP_CPU_TCK_G: XDPCN1.57 ; also on sheet 46 129 139
XDP_CPU_TDI: XDPCN1.56 ; also on sheet 46
XDP_CPU_TDO: XDPCN1.52 ; also on sheet 46
XDP_CPU_TMS_G: XDPCN1.58 ; also on sheet 46 129 139
XDP_CPU_TRST_G_N: XDPCN1.54 ; also on sheet 46 129 139
XDP_PCH_TCK0: R1901.1 ; also on sheet 90
XDP_PCH_TDI: R1899.2 R1903.1 ; also on sheet 90
XDP_PCH_TDO: R1900.2 R1904.1 ; also on sheet 90
XDP_PCH_TMS: R1898.2 R1902.1 ; also on sheet 90
XDP_PRESENT_N: R990.2 R993.1 ; also on sheet 128 138
XDP_PRESENT_R_N: R990.1 XDPCN1.60
XDP_PWRGD_RST_N: C713.1 CPLD1.N6(PB2D) R999.1 XDPCN1.41
XDP_RST_CO_N: C711.1 CPLD1.N5(PB2C) R997.1 XDPCN1.48

Not connected (* = marked no-connect by the designer): CN51 11*; CPLD1 B2(PT2A)* N13(PB5D)*; XDPCN1 MH1(NC)* MH2(NC#MH2)*

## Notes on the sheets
sheet 47
- CPU - XDP
- OBS DATA LINES
- OBS DATA LINES
- OBSFN CONTROL/STROBE
- 100 ohm - Trace length less than 4.3ns (24000mils)
- 200 ohm - 48000mils > Trace length > 24000mils
- PDG P.627
- FAB1 REV023 20150428
- Rpull-up = (960 / number of sockets connected
- to XDP) ohms = 960/2 = 480 ohm
- CAD NOTES:
  *PLACE ALL THE CAPACITORS CLOSE TO THE XDP PIN.
sheet 48
- PCH - NOA
- FAB1 REV004 20150320
sheet 49
- PCH - XDP
- JTAG'S TERMINATIONS
- Any stub length on TCK0 trace can not be more
  than 200ps.  (APPROX. 1100mils)The stub length
  should be minimized whenever possible.
- NOTE: THESE PULL UP RESISTORS SHOULD BE PLACED
  WHEN NOA INTRERFACE IS USED TO AVOID HW STRAP CORRUPTION
- FAB1 20150310
- Maximum Trace length (recommended): 1.5ns (roughly 9000mil or
  228 mm)
- FAB1 REV014 20150415
- Delete R1911
- CAD NOTES:
  * PLACE TMS, TCK & TDI TERMINATIONS WITHIN 1" FROM PCH
  * PLACE TDO TERMINATION WITHIN 1" FROM XDP CONN
sheet 50
- CPLD OTHERS
- CAD NOTE:
  PLACE DECOUPLING CAPACITORS NEAR POWER PIN ON PLD PROGRAMMING HEADER
- LATTICE IN SYSTEM PROGRAMMING HEADER.
- Place it in a line.
- Change to 84.03904.Q11
- FAB1 REV014 20150415
- CPLD1
- CPLD2
- Change to 84.03904.Q11
- FAB1 REV005 20150323
- LOCATION
- JTAG CHAIN
- JTAG MUX
- R2
- POP
- NOPOP
- R12
- POP
- NOPOP
- From BMC
- R235
- POP
- NOPOP
- Place place close to U81.
- Change to 84.03904.Q11
- R281
- POP
- NOPOP
- R334
- POP
- NOPOP
- From BMC
- R327
- POP
- NOPOP
- R351
- POP
- NOPOP
- U81
- NOPOP
- POP
- CAD NOTE:
  PLACE DECOUPLING CAPACITORS
  NEAR POWER PIN ON PLD PROGRAMMING HEADER
- Change to 84.03904.Q11
- R1110, R1111
- FAB1 REV002 20150317
- BMC JTAG SELECT
     (BMC GPIOO7)
- R1093, R1112
- NOPOP
- POP
- Setting
- R684
- 0 (Default)
- CPLD1
- 1
- CPLD2
- Change to 84.03904.Q11
- CAD NOTE: PLACE TERMINATION RESISTOR WITHIN 1" FROM CPLD.
- INTEL
- TO NGFF
- FROM CKMNG
- POP R630 to enable debug mode
- POP R631 --> PD_PERST_SRC
- TO CPLD
- FPGA JTAG CONNECTOR.
sheet 51
- CPLD FOR BOOT UP
- FAB1 20150126
- Remove dummy components
- FAB1 REV005 20150323
- FAB1 REV005 20150323
- To MEZCN0
- To PCIE0,PCIE1
- DESIGN NOTE:
  IO PINS C13 & N3 WERE GROUNDED
  TO IMPROVE THE CPLD BREAKOUT
  IO PINS N13 & B2 ARE UNCONNECTED
  TO IMPROVE THE CPLD BREAKOUT
- FAB1 REV005 20150323
